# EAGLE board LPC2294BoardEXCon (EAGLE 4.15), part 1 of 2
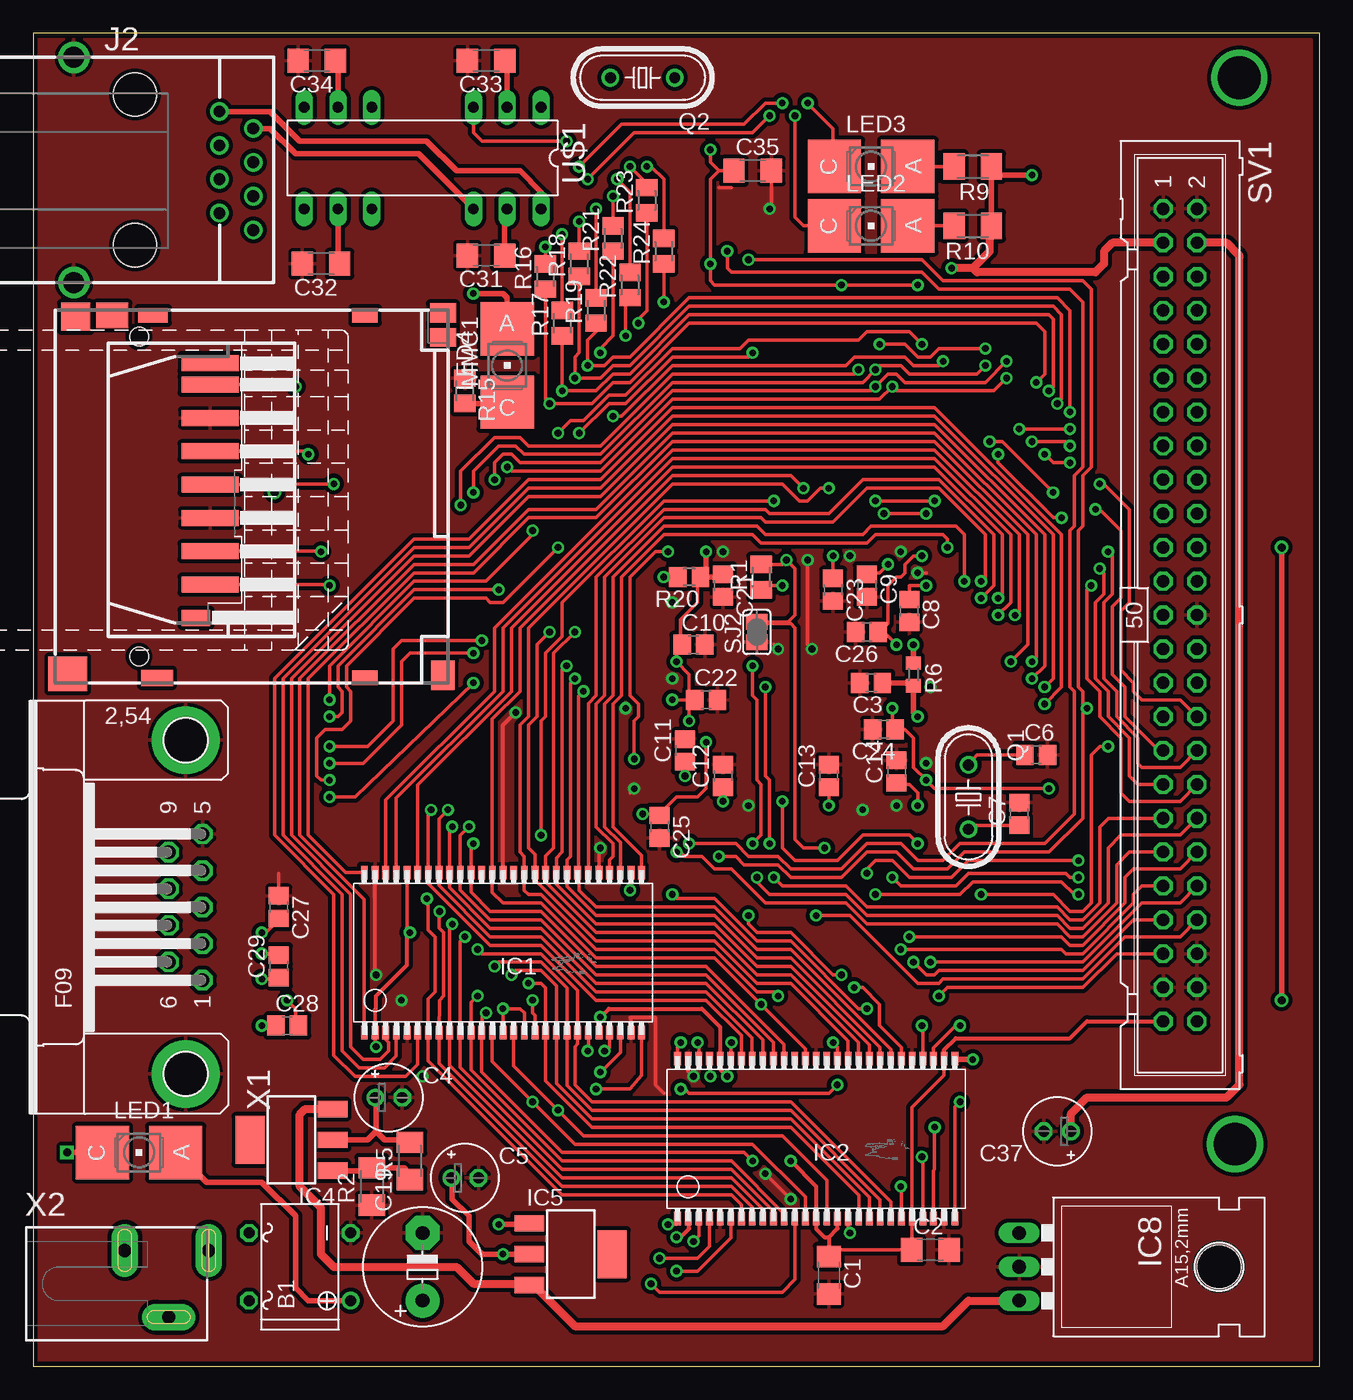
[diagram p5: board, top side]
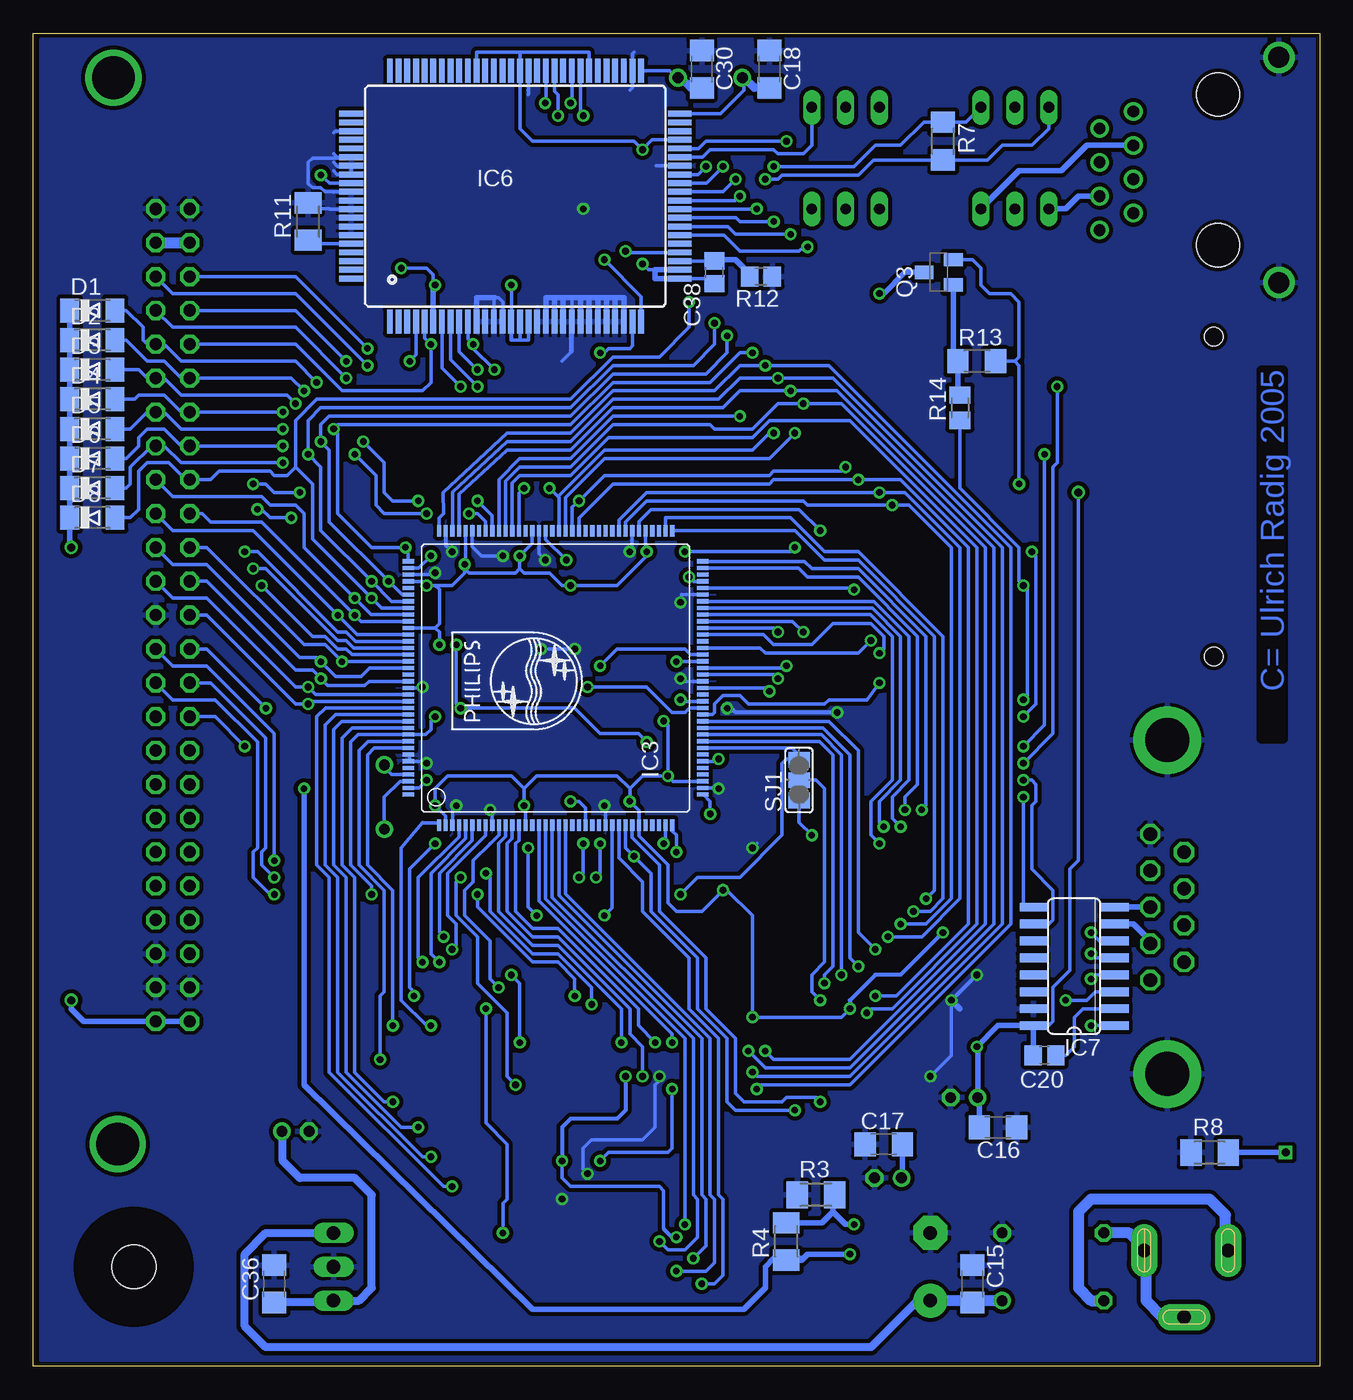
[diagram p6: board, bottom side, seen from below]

Size 96.5 x 100 mm. Coordinates in mm from the lower left corner, seen from the top.
Outline: 0,0 96.5,0 96.5,100 0,100 0,0
Copper layers (1*16): Top 0.035mm / dielectric 1.5mm / Bottom 0.035mm
Design rules "default": minimum track width 6mil, minimum drill 12mil, track to track 6mil, track to pad 6mil, pad to pad 6mil, via to via 6mil, smd to smd 6mil, copper to edge 10mil, drill to drill 8mil, minimum pad ring 10mil, minimum via ring 8mil, stop-mask expansion 4mil, vias tented up to drill 0mil, thermal gap 10mil

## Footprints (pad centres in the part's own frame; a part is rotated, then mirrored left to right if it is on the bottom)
B-DIL = drill 0.813 round: + -2.54,-3.81 | drill 0.813 octagon: - 2.54,-3.81; AC1 2.54,3.81; AC2 -2.54,3.81
C1206 = smd 1.6 x 1.8: 1 -1.4,0; 2 1.4,0
C0805 = smd 1.3 x 1.5: 1 -0.85,0; 2 0.85,0
E2-5 = drill 0.813 pad 1.27 round: + -1.016,0 | drill 0.813 pad 1.27 octagon: - 1.016,0
E5-8,5 = drill 1.016 pad 2.54 round: + -2.54,0 | drill 1.016 pad 2.54 octagon: - 2.54,0
MINIMELF = smd 1.4 x 1.8: A 1.7,0; C -1.7,0
TSOPII54 = smd 0.508 x 1.016: 1 10.401,5.601; 2 9.601,5.601; 3 8.801,5.601; 4 8.001,5.601; 5 7.201,5.601; 6 6.401,5.601; 7 5.601,5.601; 8 4.801,5.601; 9 4,5.601; 10 3.2,5.601; 11 2.4,5.601; 12 1.6,5.601; 13 0.8,5.601; 14 0,5.601; 15 -0.8,5.601; 16 -1.6,5.601; 17 -2.4,5.601; 18 -3.2,5.601; 19 -4,5.601; 20 -4.801,5.601; 21 -5.601,5.601; 22 -6.401,5.601; 23 -7.201,5.601; 24 -8.001,5.601; 25 -8.801,5.601; 26 -9.601,5.601; 27 -10.401,5.601; 28 -10.401,-6.401; 29 -9.601,-6.401; 30 -8.801,-6.401; 31 -8.001,-6.401; 32 -7.201,-6.401; 33 -6.401,-6.401; 34 -5.601,-6.401; 35 -4.801,-6.401; 36 -4,-6.401; 37 -3.2,-6.401; 38 -2.4,-6.401; 39 -1.6,-6.401; 40 -0.8,-6.401; 41 0,-6.401; 42 0.8,-6.401; 43 1.6,-6.401; 44 2.4,-6.401; 45 3.2,-6.401; 46 4,-6.401; 47 4.801,-6.401; 48 5.601,-6.401; 49 6.401,-6.401; 50 7.201,-6.401; 51 8.001,-6.401; 52 8.801,-6.401; 53 9.601,-6.401; 54 10.401,-6.401
SOT486-1 = smd 0.864 x 0.305: 1 -11,8.6; 2 -11,8.1; 3 -11,7.6; 4 -11,7.1; 5 -11,6.6; 6 -11,6.1; 7 -11,5.6; 8 -11,5.1; 9 -11,4.6; 10 -11,4.1; 11 -11,3.6; 12 -11,3.1; 13 -11,2.6; 14 -11,2.1; 15 -11,1.6; 16 -11,1.1; 17 -11,0.6; 18 -11,0.1; 19 -11,-0.4; 20 -11,-0.9; 21 -11,-1.4; 22 -11,-1.9; 23 -11,-2.4; 24 -11,-2.9; 25 -11,-3.4; 26 -11,-3.9; 27 -11,-4.4; 28 -11,-4.9; 29 -11,-5.4; 30 -11,-5.9; 31 -11,-6.4; 32 -11,-6.9; 33 -11,-7.4; 34 -11,-7.9; 35 -11,-8.4; 36 -11,-8.9; 73 11.1,-8.9; 74 11.1,-8.4; 75 11.1,-7.9; 76 11.1,-7.4; 77 11.1,-6.9; 78 11.1,-6.4; 79 11.1,-5.9; 80 11.1,-5.4; 81 11.1,-4.9; 82 11.1,-4.4; 83 11.1,-3.9; 84 11.1,-3.4; 85 11.1,-2.9; 86 11.1,-2.4; 87 11.1,-1.9; 88 11.1,-1.4; 89 11.1,-0.9; 90 11.1,-0.4; 91 11.1,0.1; 92 11.1,0.6; 93 11.1,1.1; 94 11.1,1.6; 95 11.1,2.1; 96 11.1,2.6; 97 11.1,3.1; 98 11.1,3.6; 99 11.1,4.1; 100 11.1,4.6; 101 11.1,5.1; 102 11.1,5.6; 103 11.1,6.1; 104 11.1,6.6; 105 11.1,7.1; 106 11.1,7.6; 107 11.1,8.1; 108 11.1,8.6 | smd 0.305 x 0.864: 37 -8.7,-11.2; 38 -8.2,-11.2; 39 -7.7,-11.2; 40 -7.2,-11.2; 41 -6.7,-11.2; 42 -6.2,-11.2; 43 -5.7,-11.2; 44 -5.2,-11.2; 45 -4.7,-11.2; 46 -4.2,-11.2; 47 -3.7,-11.2; 48 -3.2,-11.2; 49 -2.7,-11.2; 50 -2.2,-11.2; 51 -1.7,-11.2; 52 -1.2,-11.2; 53 -0.7,-11.2; 54 -0.2,-11.2; 55 0.3,-11.2; 56 0.8,-11.2; 57 1.3,-11.2; 58 1.8,-11.2; 59 2.3,-11.2; 60 2.8,-11.2; 61 3.3,-11.2; 62 3.8,-11.2; 63 4.3,-11.2; 64 4.8,-11.2; 65 5.3,-11.2; 66 5.8,-11.2; 67 6.3,-11.2; 68 6.8,-11.2; 69 7.3,-11.2; 70 7.8,-11.2; 71 8.3,-11.2; 72 8.8,-11.2; 109 8.8,10.9; 110 8.3,10.9; 111 7.8,10.9; 112 7.3,10.9; 113 6.8,10.9; 114 6.3,10.9; 115 5.8,10.9; 116 5.3,10.9; 117 4.8,10.9; 118 4.3,10.9; 119 3.8,10.9; 120 3.3,10.9; 121 2.8,10.9; 122 2.3,10.9; 123 1.8,10.9; 124 1.3,10.9; 125 0.8,10.9; 126 0.3,10.9; 127 -0.2,10.9; 128 -0.7,10.9; 129 -1.2,10.9; 130 -1.7,10.9; 131 -2.2,10.9; 132 -2.7,10.9; 133 -3.2,10.9; 134 -3.7,10.9; 135 -4.2,10.9; 136 -4.7,10.9; 137 -5.2,10.9; 138 -5.7,10.9; 139 -6.2,10.9; 140 -6.7,10.9; 141 -7.2,10.9; 142 -7.7,10.9; 143 -8.2,10.9; 144 -8.7,10.9
SOT-233 = smd 1.219 x 2.235: 1 -2.311,-3.099; 2 0,-3.099; 3 2.311,-3.099 | smd 3.6 x 2.2: 4 0,3.099
TQPF100 = smd 1.8 x 0.44: 1 -9.395,9.425; 2 -9.395,8.775; 3 -9.395,8.125; 4 -9.395,7.475; 5 -9.395,6.825; 6 -9.395,6.175; 7 -9.395,5.525; 8 -9.395,4.875; 9 -9.395,4.225; 10 -9.395,3.575; 11 -9.395,2.925; 12 -9.395,2.275; 13 -9.395,1.625; 14 -9.395,0.975; 15 -9.395,0.325; 16 -9.395,-0.325; 17 -9.395,-0.975; 18 -9.395,-1.625; 19 -9.395,-2.275; 20 -9.395,-2.925; 21 -9.395,-3.575; 22 -9.395,-4.225; 23 -9.395,-4.875; 24 -9.395,-5.525; 25 -9.395,-6.175; 26 -9.395,-6.825; 27 -9.395,-7.475; 28 -9.395,-8.125; 29 -9.395,-8.775; 30 -9.395,-9.425; 51 9.395,-9.425; 52 9.395,-8.775; 53 9.395,-8.125; 54 9.395,-7.475; 55 9.395,-6.825; 56 9.395,-6.175; 57 9.395,-5.525; 58 9.395,-4.875; 59 9.395,-4.225; 60 9.395,-3.575; 61 9.395,-2.925; 62 9.395,-2.275; 63 9.395,-1.625; 64 9.395,-0.975; 65 9.395,-0.325; 66 9.395,0.325; 67 9.395,0.975; 68 9.395,1.625; 69 9.395,2.275; 70 9.395,2.925; 71 9.395,3.575; 72 9.395,4.225; 73 9.395,4.875; 74 9.395,5.525; 75 9.395,6.175; 76 9.395,6.825; 77 9.395,7.475; 78 9.395,8.125; 79 9.395,8.775; 80 9.395,9.425 | smd 0.44 x 1.8: 31 -6.175,-12.32; 32 -5.525,-12.32; 33 -4.875,-12.32; 34 -4.225,-12.32; 35 -3.575,-12.32; 36 -2.925,-12.32; 37 -2.275,-12.32; 38 -1.625,-12.32; 39 -0.975,-12.32; 40 -0.325,-12.32; 41 0.325,-12.32; 42 0.975,-12.32; 43 1.625,-12.32; 44 2.275,-12.32; 45 2.925,-12.32; 46 3.575,-12.32; 47 4.225,-12.32; 48 4.875,-12.32; 49 5.525,-12.32; 50 6.175,-12.32; 81 6.175,12.32; 82 5.525,12.32; 83 4.875,12.32; 84 4.225,12.32; 85 3.575,12.32; 86 2.925,12.32; 87 2.275,12.32; 88 1.625,12.32; 89 0.975,12.32; 90 0.325,12.32; 91 -0.325,12.32; 92 -0.975,12.32; 93 -1.625,12.32; 94 -2.275,12.32; 95 -2.925,12.32; 96 -3.575,12.32; 97 -4.225,12.32; 98 -4.875,12.32; 99 -5.525,12.32; 100 -6.175,12.32
SO16@1 = smd 0.66 x 2.032: 1 -4.445,-3.073; 2 -3.175,-3.073; 3 -1.905,-3.073; 4 -0.635,-3.073; 5 0.635,-3.073; 6 1.905,-3.073; 7 3.175,-3.073; 8 4.445,-3.073; 9 4.445,3.073; 10 3.175,3.073; 11 1.905,3.073; 12 0.635,3.073; 13 -0.635,3.073; 14 -1.905,3.073; 15 -3.175,3.073; 16 -4.445,3.073
78XXL = drill 1.016 long: GND 0,-3.81; IN -2.54,-3.81; OUT 2.54,-3.81 | hole 3.302: 0,11.176
557786-1 = drill 0.889 round: 1-1 -4.445,6.35; 1-2 -3.175,8.89; 1-3 -1.905,6.35; 1-4 -0.635,8.89; 1-5 0.635,6.35; 1-6 1.905,8.89; 1-7 3.175,6.35; 1-8 4.445,8.89 | drill 1.575 pad 2.184 round: G1 -8.509,-4.572; G2 8.382,-4.572 | hole 3.251: -5.715,0; 5.588,0
P-LCC-2 = smd 4 x 4: A 0,2.75; C 0,-2.75
SD9 = smd 1.2 x 4.3: 1 -8.4,5.34; 2 -5.9,5.34; 3 -3.4,5.34; 4 -0.9,5.34; 5 1.6,5.34; 6 4.1,5.34; 7 6.6,5.34; 8 -10.025,5.34 | smd 1.2 x 2.15: 9 9.1,4.265 | smd 1.9 x 2.4: G1 -13.6,-2 | smd 1.1 x 2.2: G2 -13.6,1.05 | smd 1.1 x 1.9: G3 -13.6,16.95; G5 13.6,16.95 | smd 2.2 x 1.75: G4 13.4,22.8 | smd 1.2 x 2.4: G6 13.6,1.35 | smd 2.6 x 2.9: G7 13.3,-5.35 | smd 1.4 x 1.95: SW1 -11.95,22.8 | smd 2.1 x 2.2: SW2 -13.5,-4.75 | smd 1.45 x 1.95: SW3 -13.775,22.8 | hole 1.4: -12,0; 12,0
HC49U-V = drill 0.813 round: 1 -2.413,0; 2 2.413,0
HC49/S = drill 0.813 round: 1 -2.413,0; 2 2.413,0
SOT23-BEC = smd 1 x 1.4: B -0.95,-1.1; C 0,1.1; E 0.95,-1.1
M0805 = smd 1.3 x 1.6: 1 -0.95,0; 2 0.95,0
M1206 = smd 1.6 x 2: 1 -1.4,0; 2 1.4,0
R0603 = smd 1 x 1.1: 1 -0.85,0; 2 0.85,0
R1206 = smd 1.6 x 1.803: 1 -1.422,0; 2 1.422,0
R0805 = smd 1.3 x 1.5: 1 -0.85,0; 2 0.85,0
SJ_2 = smd 1.168 x 1.6: 1 -1.524,0; 2 0,0; 3 1.524,0
SJ = smd 1.168 x 1.6: 1 -0.762,0; 2 0.762,0
ML50 = drill 0.914 octagon: 1 -30.48,-1.27; 2 -30.48,1.27; 3 -27.94,-1.27; 4 -27.94,1.27; 5 -25.4,-1.27; 6 -25.4,1.27; 7 -22.86,-1.27; 8 -22.86,1.27; 9 -20.32,-1.27; 10 -20.32,1.27; 11 -17.78,-1.27; 12 -17.78,1.27; 13 -15.24,-1.27; 14 -15.24,1.27; 15 -12.7,-1.27; 16 -12.7,1.27; 17 -10.16,-1.27; 18 -10.16,1.27; 19 -7.62,-1.27; 20 -7.62,1.27; 21 -5.08,-1.27; 22 -5.08,1.27; 23 -2.54,-1.27; 24 -2.54,1.27; 25 0,-1.27; 26 0,1.27; 27 2.54,-1.27; 28 2.54,1.27; 29 5.08,-1.27; 30 5.08,1.27; 31 7.62,-1.27; 32 7.62,1.27; 33 10.16,-1.27; 34 10.16,1.27; 35 12.7,-1.27; 36 12.7,1.27; 37 15.24,-1.27; 38 15.24,1.27; 39 17.78,-1.27; 40 17.78,1.27; 41 20.32,-1.27; 42 20.32,1.27; 43 22.86,-1.27; 44 22.86,1.27; 45 25.4,-1.27; 46 25.4,1.27; 47 27.94,-1.27; 48 27.94,1.27; 49 30.48,-1.27; 50 30.48,1.27
DIL16/12 = drill 0.813 long: 1 -8.89,-3.81; 2 -6.35,-3.81; 3 -3.81,-3.81; 4 3.81,-3.81; 5 6.35,-3.81; 6 8.89,-3.81; 7 8.89,3.81; 8 6.35,3.81; 9 3.81,3.81; 10 -3.81,3.81; 11 -6.35,3.81; 12 -8.89,3.81
F09HP = drill 1.016 octagon: 1 -5.486,-1.27; 2 -2.743,-1.27; 3 0,-1.27; 4 2.743,-1.27; 5 5.486,-1.27; 6 -4.115,1.27; 7 -1.372,1.27; 8 1.372,1.27; 9 4.115,1.27 | drill 3.302 pad 5.08 round: G1 -12.522,0; G2 12.522,0
SCD-014-A = drill 1 pad 2 long: 1 -2.5,13.8; 2 -2.5,7.5; 3 2.5,10.8

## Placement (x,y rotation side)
B1  [B-DIL]  20,7.46 90 top
C1  100n  [C1206]  59.68,6.82 270 top
C2  100n  [C1206]  67.31,8.73 0 top
C3  100n  [C0805]  62.86,51.27 180 top
C4  10µ  [E2-5]  26.67,20.16 0 top
C5  10µ  [E2-5]  32.38,14.12 0 top
C6  33p  [C0805]  75.24,45.87 0 top
C7  33p  [C0805]  73.97,41.43 90 top
C8  100n  [C0805]  65.72,56.67 270 top
C9  100n  [C0805]  62.54,58.57 270 top
C10  100n  [C0805]  49.52,54.13 0 top
C11  100n  [C0805]  48.89,46.19 90 top
C12  100n  [C0805]  51.75,44.29 90 top
C13  100n  [C0805]  59.68,44.29 90 top
C14  100n  [C0805]  64.77,44.6 90 top
C15  100n  [C1206]  26.03,6.18 90 bottom
C16  100n  [C1206]  24.12,17.93 0 bottom
C17  100n  [C1206]  32.7,16.66 180 bottom
C18  33p  [C1206]  41.27,97.31 90 bottom
C19  470µ  [E5-8,5]  29.21,7.46 90 top
C20  100n  [C0805]  20.63,23.33 0 bottom
C21  100n  [C0805]  51.75,58.57 270 top
C22  100n  [C0805]  50.48,50 0 top
C23  100n  [C0805]  60,58.26 270 top
C24  100n  [C0805]  63.81,47.78 180 top
C25  100n  [C0805]  46.98,40.48 270 top
C26  100n  [C0805]  62.54,55.08 180 top
C27  100n  [C0805]  18.41,34.44 270 top
C28  100n  [C0805]  19.05,25.55 0 top
C29  100n  [C0805]  18.41,30 90 top
C30  33p  [C1206]  46.35,97.31 90 bottom
C31  10n  [C1206]  33.97,83.34 180 top
C32  10n  [C1206]  21.59,82.7 180 top
C33  10n  [C1206]  33.97,97.94 180 top
C34  10n  [C1206]  21.27,97.94 180 top
C35  100n  [C1206]  53.97,89.69 0 top
C36  100n  [C1206]  78.42,6.18 90 bottom
C37  10µ  [E2-5]  76.83,17.62 180 top
C38  220n  [C0805]  45.4,82.07 90 bottom
D1  [MINIMELF]  92.07,79.21 0 bottom
D2  [MINIMELF]  92.07,76.99 0 bottom
D3  [MINIMELF]  92.07,74.77 0 bottom
D4  [MINIMELF]  92.07,72.54 0 bottom
D5  [MINIMELF]  92.07,70.32 0 bottom
D6  [MINIMELF]  92.07,68.1 0 bottom
D7  [MINIMELF]  92.07,65.88 0 bottom
D8  [MINIMELF]  92.07,63.65 0 bottom
IC1  CY7C1061AV33  [TSOPII54]  35.24,30.63 180 top
IC2  CY7C1061AV33  [TSOPII54]  58.73,16.66 180 top
IC3  LPC2294  [SOT486-1]  57.46,51.59 90 bottom
IC4  LM1117  [SOT-233]  19.36,16.98 90 top
IC5  LM1117  [SOT-233]  40.32,8.41 270 top
IC6  [TQPF100]  60.32,87.78 90 bottom
IC7  MAX3232  [SO16@1]  18.41,30 90 bottom
IC8  [78XXL]  77.78,7.46 270 top
J2  [557786-1]  7.62,89.69 270 top
LED1  [P-LCC-2]  7.93,16.03 270 top
LED2  [P-LCC-2]  62.86,85.56 270 top
LED3  [P-LCC-2]  62.86,90 270 top
LED4  [P-LCC-2]  35.55,75.08 0 top
MMC1  [SD9]  7.93,65.24 270 top
Q1  12Mhz  [HC49U-V]  70.16,42.7 270 top
Q2  20MHz  [HC49/S]  45.71,96.67 180 top
Q3  BC857BSMD  [SOT23-BEC]  28.57,82.07 90 bottom
R1  10k  [M0805]  54.6,59.21 90 top
R2  390Ohm  [M1206]  25.39,13.49 90 top
R3  100Ohm  [M1206]  37.78,12.85 0 bottom
R4  220Ohm  [M1206]  40,9.36 270 bottom
R5  240Ohm  [M1206]  28.25,15.39 90 top
R6  10k  [R0603]  66.04,51.91 270 top
R7  220  [R1206]  28.25,91.91 270 bottom
R8  470  [M1206]  8.25,16.03 0 bottom
R9  1k  [M1206]  70.48,90 180 top
R10  1k  [M1206]  70.48,85.56 180 top
R11  27k  [M1206]  75.88,85.88 270 bottom
R12  47k  [R0805]  41.9,81.75 180 bottom
R13  10K  [R1206]  25.71,75.4 0 bottom
R14  470  [M0805]  26.98,71.91 90 bottom
R15  100  [M0805]  32.38,73.18 270 top
R16  [M0805]  38.41,81.75 90 top
R17  [M0805]  39.68,78.26 90 top
R18  [M0805]  40.95,82.7 90 top
R19  [M0805]  42.22,79.21 90 top
R20  10k  [R0805]  49.21,59.21 180 top
R21  [M0805]  43.49,84.61 90 top
R22  [M0805]  44.76,81.11 90 top
R23  [M0805]  46.03,87.46 90 top
R24  [M0805]  47.3,83.65 90 top
SJ1  [SJ_2]  39.05,43.97 90 bottom
SJ2  [SJ]  54.29,55.08 90 top
SV1  [ML50]  86.04,56.35 270 top
U$1  [DIL16/12]  29.21,90.64 180 top
X1  [F09HP]  11.42,34.44 90 top
X2  [SCD-014-A]  -0.64,6.18 270 top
